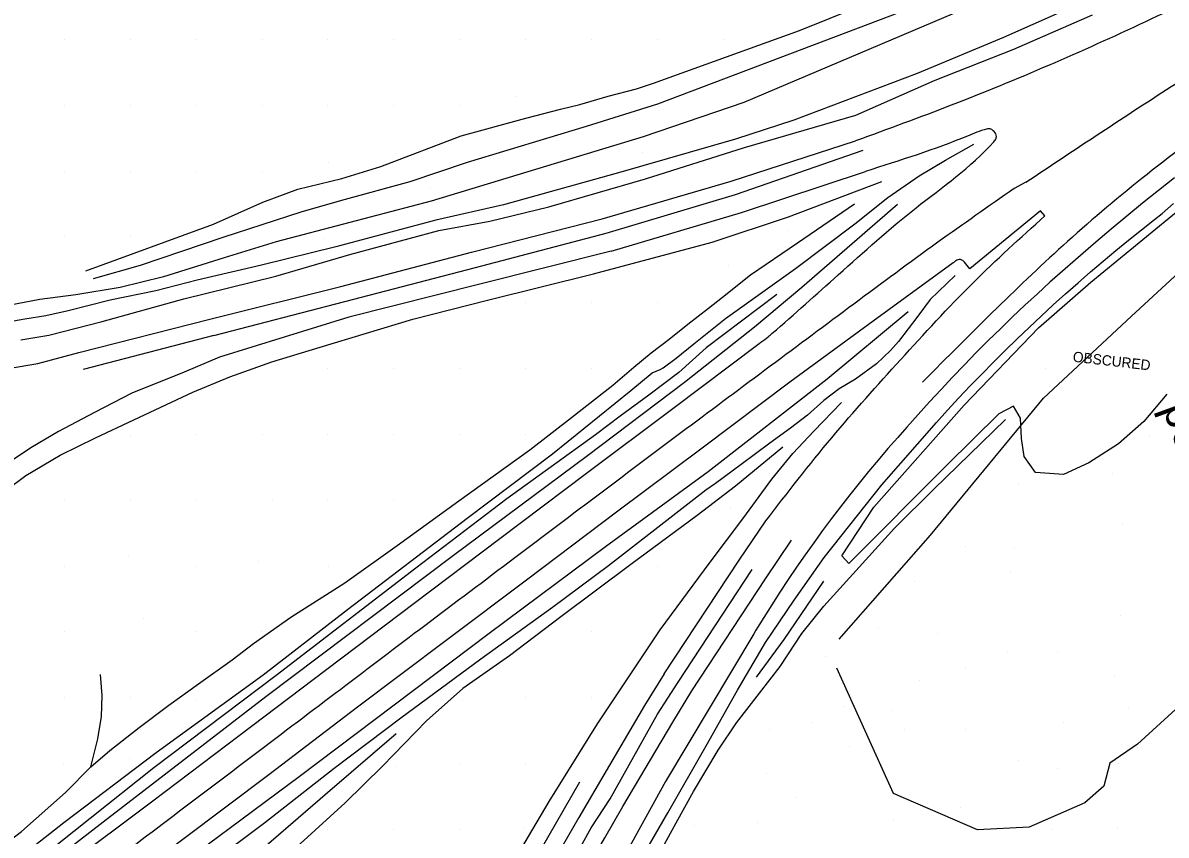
# Model space of a CAD drawing. Extents: x 524772 to 528246, y 273285 to 283088.
# Drawn here: x 526864.4 to 527033.7, y 277382.3 to 277502.6 of the extents above; entities that cross this region are included whole.
import ezdxf

# ---------------------------------------------------------------- set-up
doc = ezdxf.new("R2010")
doc.units = 0
for name, color, linetype in [('Exist DTM Crownline', 7, 'Continuous'), ('Exist DTM Spot Elevation CELL', 7, 'Continuous'), ('Exist Roads EOP', 7, 'Continuous'), ('Old_Level_12', 7, 'Continuous'), ('PH Exist DTM Breakline', 7, 'Continuous'), ('PH Exist DTM Obscure Area', 7, 'Continuous'), ('PH Exist DTM Obscure Area Text', 7, 'Continuous'), ('PH Exist DTM Point', 7, 'Continuous')]:
    doc.layers.add(name, color=color, linetype=linetype)

msp = doc.modelspace()

# ---------------------------------------------------------------- linework, layer by layer
at = {"layer": 'Exist DTM Crownline'}
for p, q in [((527012.9, 277479), (527011.17, 277478.06)), ((526892.71, 277456.3), (526873.36, 277451.26)), ((526961.42, 277404.92), (526972.4, 277421.64))]:
    msp.add_line(p, q, dxfattribs=at)
for points in [[(526950.76, 277471.47), (526969.93, 277477.18), (526988.83, 277483.73)], [(526892.71, 277456.3), (526912.07, 277461.35), (526931.42, 277466.39), (526950.76, 277471.47)], [(526958.38, 277400.18), (526961.42, 277404.92)], [(526928.61, 277348.41), (526931.35, 277353), (526938.32, 277365.86), (526941.36, 277370.32), (526948.55, 277383.35), (526951.36, 277387.64), (526958.38, 277400.18)]]:
    msp.add_lwpolyline(points, dxfattribs=at)
for points in [[(527012.9, 277479), (527035.13, 277493.63), (527047.79, 277501.59), (527061.59, 277510.01), (527074.93, 277517.83), (527087.69, 277524.92), (527101.22, 277532.16), (527115.31, 277539.39), (527129.4, 277546.52), (527143.33, 277553.09), (527157.2, 277559.38), (527172, 277565.61), (527185.97, 277571.18), (527200.44, 277576.75), (527213.91, 277581.57), (527228.29, 277586.39), (527242.7, 277590.91), (527257.14, 277595.19), (527271.79, 277599.28)], [(527011.17, 277478.06), (526999.87, 277470.1), (526987.44, 277460.96), (526975.06, 277451.74), (526962.63, 277442.45), (526949.98, 277432.96), (526937.25, 277423.35), (526923.93, 277413.31), (526911.47, 277403.88), (526898.66, 277394.17), (526886.05, 277384.62), (526872.77, 277374.62), (526860.1, 277365.18), (526847.11, 277355.34)]]:
    msp.add_spline(points, degree=3, dxfattribs=at)
at = {"layer": 'Exist DTM Spot Elevation CELL'}
for p, q in [((527015.81, 277451.36), (527015.81, 277451.36)), ((527031.15, 277441.4), (527031.15, 277441.4)), ((527011.25, 277424.94), (527011.25, 277424.94)), ((527017.53, 277409.42), (527017.53, 277409.42))]:
    msp.add_line(p, q, dxfattribs=at)
at = {"layer": 'Exist Roads EOP'}
for points in [[(526841.46, 277530.19), (526834.27, 277520.29), (526832.19, 277517.37), (526830.46, 277513.94), (526829.51, 277511.17), (526829.02, 277508.93), (526829.14, 277505.29), (526832.21, 277494.98), (526836.64, 277479.16), (526841.48, 277462.31), (526842.66, 277459.33), (526844.38, 277456.84), (526846.59, 277454.5), (526848.53, 277453.24), (526850.41, 277452.23), (526852.97, 277451.57), (526857.59, 277451.08), (526862.25, 277451.43), (526866.66, 277452.17), (526872.7, 277453.78), (526892.08, 277458.72)], [(526950.18, 277473.59), (526969.29, 277479.18), (526987.67, 277485.12)], [(526951.5, 277468.77), (526970.79, 277474.52), (526989.14, 277480.6)], [(526892.08, 277458.72), (526911.49, 277463.57), (526930.84, 277468.62), (526950.18, 277473.59)], [(527015.73, 277474.03), (527015.06, 277474.78), (527004.59, 277466.19), (527003.84, 277467.15)], [(526951.5, 277468.77), (526932.07, 277463.88), (526912.67, 277459.03), (526893.54, 277453.11)], [(527002.14, 277467.05), (526990.29, 277458.43), (526977.96, 277449.39), (526964.96, 277439.62), (526952.28, 277430.11), (526939.19, 277420.22), (526927.11, 277411.11), (526913.98, 277401.22), (526900.84, 277391.21), (526888.12, 277381.63), (526874.88, 277371.64), (526862.48, 277362.33), (526849.34, 277352.38)], [(526844.8, 277358.15), (526857.97, 277368.04), (526870.67, 277377.62), (526883.64, 277387.37), (526896.44, 277397.03), (526909.42, 277406.87), (526922.35, 277416.65), (526935.05, 277426.24), (526947.88, 277435.92), (526960.62, 277445.47), (526973.4, 277455.12), (526973.69, 277455.3)], [(526893.54, 277453.11), (526888.29, 277450.86), (526880.55, 277447.74), (526875.02, 277444.87), (526869.69, 277442.09), (526865.6, 277439.64), (526862.45, 277437.52), (526857.41, 277433.15), (526854.01, 277430.64), (526851.28, 277427.54), (526850.11, 277424.79), (526849.64, 277423.18), (526849.44, 277420.58), (526850.25, 277416.42), (526854.3, 277399.73), (526857.14, 277387.96)], [(526959.37, 277406.17), (526970.44, 277423.02), (526974.39, 277428.82)], [(526963.47, 277403.67), (526974.36, 277420.25), (526978.21, 277425.97)], [(526959.37, 277406.17), (526956.47, 277401.5)], [(526960.63, 277399.04), (526963.47, 277403.67)], [(526956.47, 277401.5), (526949.1, 277388.94), (526946.71, 277384.91), (526939.1, 277371.62), (526936.5, 277367.19), (526929.1, 277354.3), (526926.43, 277349.54)], [(526930.59, 277347.23), (526933.26, 277351.9), (526940.57, 277364.56), (526943.26, 277369.22), (526950.56, 277381.87), (526953.26, 277386.54), (526960.63, 277399.04)]]:
    msp.add_lwpolyline(points, dxfattribs=at)
for points in [[(527270.78, 277603.37), (527256.06, 277599.09), (527241.65, 277594.75), (527227.06, 277590.17), (527212.47, 277585.21), (527198.44, 277580.12), (527184.35, 277574.63), (527170.36, 277569.05), (527155.19, 277563.06), (527141.3, 277557.34), (527127, 277550.99), (527112.8, 277544.51), (527098.63, 277537.78), (527084.82, 277531.02), (527071.32, 277523.94), (527058.01, 277516.8), (527044.38, 277509.59), (527030.61, 277502.78), (527016.27, 277496.31), (527001.86, 277490.41), (526987.67, 277485.12)], [(527272.57, 277596.68), (527258.04, 277592.42), (527243.99, 277587.67), (527229.51, 277583.19), (527215.42, 277578.37), (527201.07, 277573.4), (527187.28, 277567.87), (527173.13, 277562.03), (527158.7, 277555.6), (527145.65, 277549.11), (527132.3, 277542.12), (527118.3, 277534.55), (527104.37, 277526.77), (527090.79, 277518.88), (527078.39, 277511.74), (527065.58, 277504.12), (527056.77, 277498.41), (527052.06, 277495.3), (527043.57, 277489.61), (527030.84, 277480.16), (527019.08, 277470.24), (527008.57, 277460.31), (526997.6, 277449.4)], [(526973.69, 277455.3), (526974.77, 277456.11), (526975.37, 277456.62), (526985.14, 277465.29), (526996.64, 277475.21), (527008.16, 277484.99), (527008.53, 277485.55), (527008.53, 277485.99), (527008.07, 277486.64), (527007.61, 277486.91), (527007.08, 277486.86), (527004.27, 277485.85), (526989.14, 277480.6)], [(526974.39, 277428.82), (526984.16, 277441.15), (526994.37, 277452.72), (527005.03, 277464.07), (527015.73, 277474.03)], [(527003.84, 277467.15), (527003.25, 277467.54), (527002.83, 277467.52), (527002.53, 277467.36), (527002.14, 277467.05)]]:
    msp.add_spline(points, degree=3, dxfattribs=at)
at = {"layer": 'Old_Level_12'}
msp.add_lwpolyline([(526985.25, 277411.31), (526998.8, 277426.7), (527015.52, 277447.03), (527028.53, 277459.17), (527038.72, 277468.55), (527050.4, 277479.65), (527060.21, 277482.96), (527057.46, 277470.38), (527062.53, 277453.28), (527064.85, 277445.08), (527064.96, 277426.88), (527062.27, 277415.48), (527049.18, 277410.15), (527037.93, 277403.49), (527029.44, 277395.78), (527025.35, 277392.96), (527024.45, 277389.54), (527021.62, 277387.08), (527013.37, 277383.47), (527005.76, 277383.08), (526993.31, 277388.45), (526984.9, 277407.03)], dxfattribs=at)
at = {"layer": 'PH Exist DTM Breakline'}
for points in [[(527063.63, 277534.95), (527050.12, 277528.7), (527017.93, 277514.39), (527007.64, 277509.27), (526958.35, 277490.57), (526947.83, 277487.25), (526930.21, 277481.91), (526921.71, 277479.07), (526911.59, 277476.32), (526905.56, 277474.55), (526894.03, 277470.8), (526881.77, 277466.68), (526874.81, 277464.71)], [(527062.35, 277531.86), (527019.31, 277510.96), (527008.52, 277506.7), (526971.15, 277490.83), (526956.27, 277485.74), (526924.85, 277476.2), (526912.85, 277473.02), (526901.93, 277470.15), (526894.22, 277467.82), (526885.23, 277465), (526878.81, 277463.4), (526872.26, 277462.31), (526866.92, 277461.65), (526860.41, 277460.41)], [(526873.74, 277465.87), (526892.65, 277472.8), (526899.96, 277476.07), (526905.11, 277477.98), (526911.66, 277479.57), (526917.44, 277481.31), (526929.3, 277485.88), (526938.87, 277488.48), (526944.02, 277489.82), (526946.88, 277490.54), (526951.07, 277491.74), (526955.27, 277492.86), (526957.79, 277493.7), (526979.4, 277501.48), (526997.28, 277508.73), (527005.2, 277511.71), (527009.21, 277513.32), (527012.82, 277514.99), (527019.04, 277517.43), (527025.7, 277519.5), (527035.15, 277523.43)], [(527023.06, 277506.47), (527009.57, 277500.42), (526996.83, 277495.12), (526978.53, 277488.21), (526969.9, 277485.38), (526952.94, 277480.51), (526935.56, 277475.65), (526925.56, 277473.39), (526910.73, 277469.44), (526899.74, 277466.74), (526890.23, 277464.5), (526884.11, 277462.93), (526877.36, 277461.51), (526871.11, 277459.97), (526867.83, 277459.21), (526864.72, 277458.72), (526860.79, 277458.02)], [(526864.14, 277455.67), (526868.26, 277456.37), (526876.17, 277458.36), (526888.25, 277461.75), (526901.87, 277465.07), (526912.84, 277468.3), (526926.02, 277471.87), (526933.54, 277473.26), (526942.28, 277475.37), (526956.61, 277479.5), (526971.24, 277484.17), (526987.71, 277488.95), (526999.47, 277494.11), (527011.1, 277498.73), (527022.76, 277503.81)], [(526845.18, 277363.98), (526864.26, 277379.28), (526870.49, 277384.16), (526884.16, 277394.51), (526899.98, 277406.05), (526912.48, 277415.71), (526930.2, 277429.24), (526942.85, 277438.76), (526954.42, 277448.17), (526957.59, 277450.76), (526958.75, 277451.28), (526959.2, 277451.49), (526961.14, 277452.94), (526963.73, 277455.07), (526968.45, 277458.83), (526978.78, 277466.21), (526987.6, 277472.82), (526992.45, 277476.75), (526997.11, 277479.95), (527001.01, 277482.26), (527005.21, 277484.66)], [(526858.12, 277407.13), (526856.65, 277414.99), (526856.13, 277418.93), (526856.04, 277421.57), (526856.32, 277424.28), (526857.68, 277428.15), (526859.54, 277430.88), (526861.96, 277433.41), (526864.88, 277435.57), (526869.97, 277438.57), (526875.16, 277441.12), (526880.83, 277443.83), (526889.58, 277447.88), (526895.05, 277450.17), (526901.26, 277452.41), (526908.44, 277454.56), (526922.16, 277458.73), (526933.4, 277461.57), (526948.9, 277465.43), (526966.46, 277470.14), (526977.77, 277473.88), (526991.6, 277479.12)], [(527034.89, 277479.67), (527032.53, 277477.79), (527030.19, 277475.9), (527027.86, 277473.98), (527025.55, 277472.05), (527023.25, 277470.1), (527022.14, 277469.15), (527020.23, 277467.51), (527018.34, 277465.85), (527016.47, 277464.18), (527014.61, 277462.49), (527012.76, 277460.78), (527010.94, 277459.05), (527009.13, 277457.3), (527007.34, 277455.54), (527005.56, 277453.76), (527003.8, 277451.97), (527002.06, 277450.15), (527000.34, 277448.32), (526998.63, 277446.48), (526996.94, 277444.61), (526995.27, 277442.73), (526993.94, 277441.21), (526992.48, 277439.54), (526991.05, 277437.85), (526989.63, 277436.14), (526988.23, 277434.42), (526986.85, 277432.69), (526985.48, 277430.94), (526984.14, 277429.17), (526982.82, 277427.39), (526981.52, 277425.6), (526980.23, 277423.79), (526978.97, 277421.96), (526977.72, 277420.13), (526976.5, 277418.28), (526975.3, 277416.41), (526974.12, 277414.54), (526972.95, 277412.65), (526972.61, 277412.08), (526959.55, 277390.22), (526945.78, 277365.23)], [(526993.89, 277475.7), (526979.73, 277463.41), (526972.73, 277457.55), (526962.38, 277449.35), (526948.03, 277438.46), (526928.18, 277423.69), (526900.38, 277402.78), (526876.31, 277384.23), (526865.35, 277375.69)], [(526953.16, 277373.9), (526959.89, 277385.6), (526965.58, 277395.53), (526970.19, 277403.75), (526974.35, 277410.82), (526978.6, 277417.1), (526983.05, 277423.39), (526991.6, 277434.19), (526999.67, 277443.43), (527001.32, 277445.24), (527002.99, 277447.04), (527004.67, 277448.82), (527006.38, 277450.59), (527008.1, 277452.34), (527009.84, 277454.07), (527011.59, 277455.79), (527013.37, 277457.49), (527015.16, 277459.17), (527016.96, 277460.83), (527018.78, 277462.48), (527020.62, 277464.1), (527022.47, 277465.71), (527024.34, 277467.31), (527026.22, 277468.88), (527028.12, 277470.43), (527030.03, 277471.97), (527031.96, 277473.49), (527033.1, 277474.37), (527034.76, 277475.84)], [(526972.14, 277465.27), (526979.11, 277470.04), (526987.55, 277475.79)], [(526843.35, 277366.92), (526864.2, 277382.82), (526870.73, 277388.59), (526874.5, 277392.38), (526877.3, 277394.83), (526881.64, 277398.24), (526886.04, 277401.52), (526890.44, 277404.71), (526895.39, 277408.26), (526898.59, 277410.65), (526904.09, 277414.58), (526912.1, 277419.66), (526919.82, 277425.2), (526928.97, 277431.81), (526939.49, 277439.34), (526945.63, 277444.17), (526951.78, 277448.94), (526954.88, 277451.63), (526957.42, 277453.72), (526960.09, 277455.77), (526962.86, 277457.96), (526965.94, 277460.36), (526968, 277462), (526972.14, 277465.27)], [(527002.43, 277465.2), (526998.75, 277461.63), (526996.92, 277459.16), (526994.06, 277455.4), (526992.85, 277454.08), (526990.78, 277452.11), (526987.68, 277449.84), (526985.25, 277448.4), (526982.97, 277446.68), (526980.56, 277444.5), (526978.04, 277442.59), (526974.98, 277440.36), (526970.78, 277437.2), (526966.95, 277434.39), (526965.55, 277433.37), (526960.64, 277429.57), (526951.13, 277422.18), (526942.81, 277415.99), (526932.21, 277408.35), (526920.37, 277399.6), (526910.53, 277392.14), (526900.23, 277384.1), (526882.04, 277370.44)], [(526976.02, 277462.36), (526965.59, 277454.45), (526961.52, 277450.82), (526957.09, 277447.48), (526952.83, 277444.33), (526949.19, 277441.56), (526936.05, 277432.12), (526922.6, 277421.83), (526901.9, 277405.95), (526883.79, 277392.25), (526864.96, 277377.26), (526845.57, 277362.3)], [(526847.82, 277347.7), (526868.14, 277363.19), (526883.29, 277374.56), (526905.35, 277390.98), (526933.45, 277412.19), (526950.67, 277425.04), (526965.88, 277436.15), (526983.48, 277449.89), (526995.5, 277459.84)], [(526936.22, 277376.91), (526942.31, 277387.25), (526949.47, 277398.79), (526958.75, 277412.71), (526966.15, 277422.71), (526971, 277429.15), (526975.3, 277435), (526978.39, 277438.81), (526981.52, 277442.15), (526985.61, 277446.37)], [(526951.26, 277365.19), (526957.42, 277377.32), (526961.14, 277384.11), (526963.71, 277388.74), (526967.36, 277394.88), (526970.07, 277398.91), (526973.47, 277403.31), (526976.54, 277407.26), (526979.75, 277412.17), (526982.98, 277416.19), (526993.46, 277427.78), (526999.3, 277433.54), (527009.91, 277443.87)], [(526976.94, 277439.76), (526969.93, 277433.96), (526964.24, 277429.65), (526954.42, 277422.4), (526944.07, 277414.62), (526936.46, 277408.84), (526929.57, 277404.02), (526924.19, 277399.21), (526917.68, 277392.52), (526912.12, 277387.09), (526905.47, 277380.98), (526898.82, 277375.07), (526890.33, 277368.18), (526884.81, 277363.33), (526880.05, 277358.48)], [(526982.95, 277419.93), (526977.06, 277411.27), (526973, 277405.67)], [(526874.5, 277392.38), (526875.53, 277396.53), (526876.04, 277399.87), (526876.16, 277402.99), (526875.94, 277406.1)], [(526849.2, 277341.8), (526869.42, 277357.02), (526874.51, 277360.85), (526877.93, 277363.28), (526882.38, 277366.62), (526890.38, 277372.7), (526900.11, 277380.44), (526909.54, 277388.58), (526919.68, 277397.33)], [(526882.54, 277308.94), (526885.46, 277307.93), (526888.49, 277307.72), (526892.1, 277307.74), (526894.46, 277308.15), (526896.83, 277309.52), (526899.05, 277311.33), (526901.68, 277314.44), (526903.9, 277317.82), (526907.23, 277323.66), (526914.04, 277334.8), (526927.3, 277356.67), (526937.58, 277374.01), (526946.87, 277390.18)]]:
    msp.add_lwpolyline(points, dxfattribs=at)
at = {"layer": 'PH Exist DTM Obscure Area'}
msp.add_lwpolyline([(527033.79, 277447.59), (527030.39, 277443.54), (527026.61, 277440.27), (527022.2, 277437.43), (527018.47, 277435.7), (527014.34, 277435.98), (527012.65, 277438.38), (527012.26, 277441.06), (527012.09, 277444.04), (527011.06, 277445.83), (527008.88, 277444.71), (527001.22, 277437.08), (526986.72, 277422.54), (526985.64, 277423.64), (526990.38, 277430.89), (527003.77, 277445.97), (527014.78, 277457.45), (527022.51, 277464.18), (527035.99, 277475.25)], dxfattribs=at)
at = {"layer": 'PH Exist DTM Point'}
for p, q in [((526870.58, 277500.16), (526870.58, 277500.16)), ((526880.33, 277500.16), (526880.33, 277500.16)), ((526890.09, 277500.16), (526890.09, 277500.16)), ((526899.84, 277500.16), (526899.84, 277500.16)), ((526909.59, 277500.16), (526909.59, 277500.16)), ((526919.35, 277500.16), (526919.35, 277500.16)), ((526929.1, 277500.16), (526929.1, 277500.16)), ((526938.85, 277500.16), (526938.85, 277500.16)), ((526948.61, 277500.16), (526948.61, 277500.16)), ((526958.36, 277500.16), (526958.36, 277500.16)), ((526968.11, 277500.21), (526968.11, 277500.21)), ((526937.31, 277491.68), (526937.31, 277491.68)), ((526870.58, 277490.41), (526870.58, 277490.41)), ((526880.33, 277490.41), (526880.33, 277490.41)), ((526890.09, 277490.41), (526890.09, 277490.41)), ((526899.84, 277490.41), (526899.84, 277490.41)), ((526909.59, 277490.41), (526909.59, 277490.41)), ((526919.35, 277490.41), (526919.35, 277490.41)), ((526929.1, 277490.41), (526929.1, 277490.41)), ((526956.08, 277483.37), (526956.08, 277483.37)), ((526870.58, 277480.66), (526870.58, 277480.66)), ((526880.33, 277480.66), (526880.33, 277480.66)), ((526890.09, 277480.66), (526890.09, 277480.66)), ((526899.84, 277480.66), (526899.84, 277480.66)), ((526909.74, 277481.99), (526909.74, 277481.99)), ((526924.76, 277478.07), (526924.76, 277478.07)), ((526870.58, 277470.9), (526870.58, 277470.9)), ((526880.33, 277470.9), (526880.33, 277470.9)), ((526908.96, 277470.69), (526908.96, 277470.69)), ((526977.73, 277471.85), (526977.73, 277471.85)), ((526968.95, 277466.7), (526968.95, 277466.7)), ((526938.85, 277461.15), (526938.85, 277461.15)), ((526948.61, 277461.15), (526948.61, 277461.15)), ((526958.39, 277461.14), (526958.39, 277461.14)), ((526909.56, 277451.4), (526909.56, 277451.4)), ((526919.32, 277451.4), (526919.32, 277451.4)), ((526929.1, 277451.39), (526929.1, 277451.39)), ((526938.85, 277451.39), (526938.85, 277451.39)), ((526948.61, 277451.39), (526948.61, 277451.39)), ((526890.09, 277441.67), (526890.09, 277441.67)), ((526899.87, 277441.64), (526899.87, 277441.64)), ((526909.59, 277441.64), (526909.59, 277441.64)), ((526919.35, 277441.64), (526919.35, 277441.64)), ((526929.1, 277441.64), (526929.1, 277441.64)), ((526938.85, 277441.64), (526938.85, 277441.64)), ((526880.36, 277441.34), (526880.36, 277441.34)), ((527008.31, 277437.75), (527008.31, 277437.75)), ((527025.69, 277435.92), (527025.69, 277435.92)), ((527011.83, 277434.31), (527011.83, 277434.31)), ((526870.58, 277431.89), (526870.58, 277431.89)), ((526880.33, 277431.89), (526880.33, 277431.89)), ((526890.09, 277431.89), (526890.09, 277431.89)), ((526901.35, 277431.94), (526901.35, 277431.94)), ((526909.59, 277431.89), (526909.59, 277431.89)), ((526919.35, 277431.89), (526919.35, 277431.89)), ((526969.18, 277430.63), (526969.18, 277430.63)), ((527027.26, 277428.31), (527027.26, 277428.31)), ((527004, 277425), (527004, 277425)), ((526880.07, 277423.69), (526880.07, 277423.69)), ((526899.28, 277422.82), (526899.28, 277422.82)), ((526870.58, 277422.13), (526870.58, 277422.13)), ((526890.08, 277422.11), (526890.08, 277422.11)), ((526909.62, 277422.13), (526909.62, 277422.13)), ((526958.36, 277422.13), (526958.36, 277422.13)), ((527010.61, 277421.15), (527010.61, 277421.15)), ((526996.4, 277419.93), (526996.4, 277419.93)), ((526882.29, 277414.42), (526882.29, 277414.42)), ((527026.98, 277414.85), (527026.98, 277414.85)), ((526991.06, 277413.03), (526991.06, 277413.03)), ((526870.58, 277412.38), (526870.58, 277412.38)), ((526890.09, 277412.38), (526890.09, 277412.38)), ((526899.77, 277412.5), (526899.77, 277412.5)), ((526948.61, 277412.38), (526948.61, 277412.38)), ((526999.79, 277412.13), (526999.79, 277412.13)), ((527010.15, 277409.42), (527010.15, 277409.42)), ((526983.22, 277408.73), (526983.22, 277408.73)), ((527004, 277407.01), (527004, 277407.01)), ((527025.95, 277405.95), (527025.95, 277405.95)), ((526997.15, 277405.18), (526997.15, 277405.18)), ((526870.58, 277402.63), (526870.58, 277402.63)), ((526880.33, 277402.63), (526880.33, 277402.63)), ((526938.85, 277402.63), (526938.85, 277402.63)), ((526948.61, 277402.63), (526948.61, 277402.63)), ((526890.17, 277402.41), (526890.17, 277402.41)), ((526929.44, 277402.18), (526929.44, 277402.18)), ((526985.85, 277401.41), (526985.85, 277401.41)), ((526993.12, 277400.82), (526993.12, 277400.82)), ((527028.11, 277401.21), (527028.11, 277401.21)), ((526974.9, 277397.91), (526974.9, 277397.91)), ((526981.36, 277399.02), (526981.36, 277399.02)), ((526995, 277398), (526995, 277398)), ((527004, 277398), (527004, 277398)), ((527018.52, 277398.95), (527018.52, 277398.95)), ((526986.75, 277395.36), (526986.75, 277395.36)), ((526870.43, 277392.97), (526870.43, 277392.97)), ((526880.21, 277393.68), (526880.21, 277393.68)), ((526919.78, 277392.42), (526919.78, 277392.42)), ((526929.1, 277392.87), (526929.1, 277392.87)), ((526938.85, 277392.87), (526938.85, 277392.87)), ((527011.85, 277393.41), (527011.85, 277393.41)), ((527026.64, 277392.87), (527026.64, 277392.87)), ((526974.56, 277391.38), (526974.56, 277391.38)), ((527017.65, 277392.18), (527017.65, 277392.18)), ((526978.95, 277387.92), (526978.95, 277387.92)), ((527003.25, 277386.44), (527003.25, 277386.44)), ((526973.13, 277384.2), (526973.13, 277384.2)), ((526993.24, 277384.4), (526993.24, 277384.4)), ((526909.59, 277383.12), (526909.59, 277383.12)), ((526919.35, 277383.12), (526919.35, 277383.12)), ((526929.1, 277383.12), (526929.1, 277383.12)), ((526938.63, 277383.42), (526938.63, 277383.42)), ((526963.84, 277383.71), (526963.84, 277383.71)), ((527016.89, 277383.15), (527016.89, 277383.15)), ((527026.5, 277383.37), (527026.5, 277383.37))]:
    msp.add_line(p, q, dxfattribs=at)

# ---------------------------------------------------------------- texts
at = {"layer": 'Old_Level_12'}
msp.add_text('obscured', height=5, rotation=110, dxfattribs=at).set_placement((527046.08, 277421.08))
at = {"layer": 'PH Exist DTM Obscure Area Text'}
msp.add_text('OBSCURED', height=1.524, rotation=353.4693, dxfattribs=at).set_placement((527019.79, 277452.43))

doc.saveas('drawing.dxf')
